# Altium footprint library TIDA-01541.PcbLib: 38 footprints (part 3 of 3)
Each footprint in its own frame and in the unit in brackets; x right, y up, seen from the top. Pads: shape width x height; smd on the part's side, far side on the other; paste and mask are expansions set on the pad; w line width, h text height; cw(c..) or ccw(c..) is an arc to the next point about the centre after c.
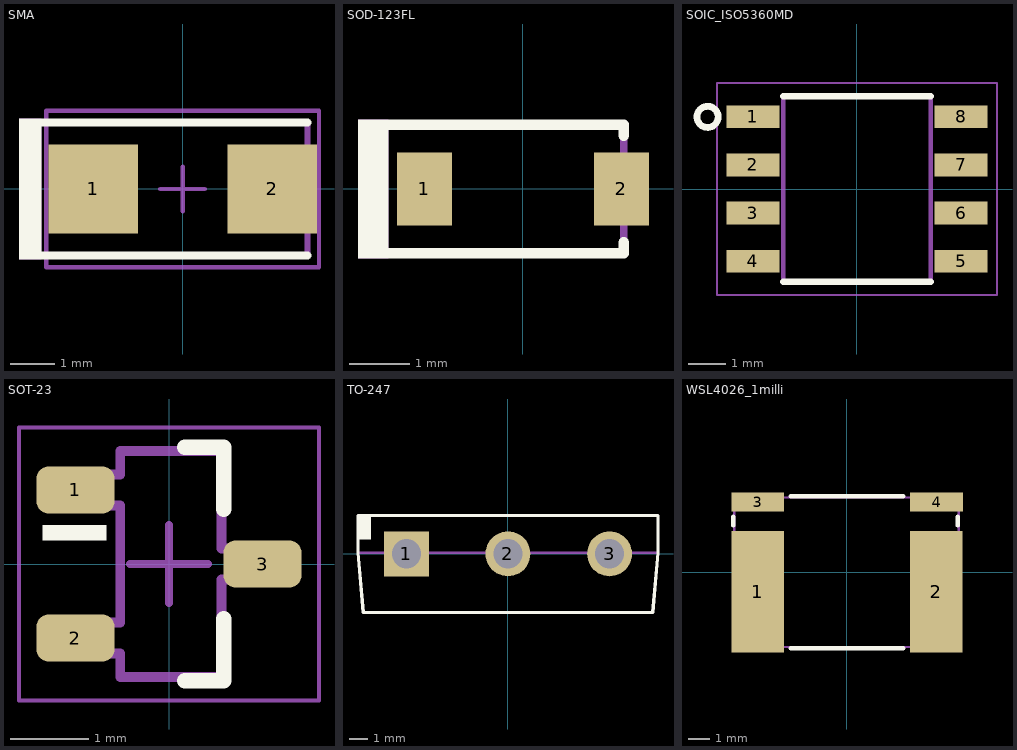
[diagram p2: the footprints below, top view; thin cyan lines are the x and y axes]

## SMA [mm] "Molded Diode, 2-Leads, Body 4.3x2.6mm, IPC Medium Density, based on OnSemi component dimensions and land pattern"
height 2.27
pads (2):
  rect 2x2 smd: 1(-2,0) 2(2,0)
Top Overlay:
  rectangle: -3.658,-1.575 -3.15,1.575
  lines w0.178: -3.327,-1.486 2.794,-1.486 ; -3.327,1.486 2.794,1.486
Mechanical 5:
  rectangle: -3.658,-1.575 -3.15,1.575
  lines w0.127: -3.327,-1.486 2.794,-1.486 2.794,1.486 -3.327,1.486
  text ".Designator" at -0.666,-0.182 h0.76
Mechanical 15:
  lines w0.1: -0.5,0 0.5,0 ; 0,-0.5 0,0.5 ; -3.05,-1.75 3.05,-1.75 3.05,1.75 -3.05,1.75 -3.05,-1.75
3D body "SMA_nominal.stp": height 2.42, standoff 0.02, extent -2.6,-1.3 2.6,1.3

## SOD-123FL [mm] "Copied from SOD-123"
height 0.991
pads (2):
  rect 0.915x1.22 smd: 1(-1.637,0) 2(1.637,0)
Top Overlay:
  rectangle: -2.743,-1.156 -2.235,1.156
  lines w0.178: -2.438,-1.067 1.676,-1.067 1.676,-0.889 ; -2.438,1.067 1.676,1.067 1.676,0.889
Mechanical 5:
  rectangle: -2.743,-1.156 -2.235,1.156
  lines w0.127: -2.438,-1.067 1.676,-1.067 1.676,1.067 -2.438,1.067
  text ".Designator" at 0.406,-0.635 h0.76
3D body "SOD-123FL.stp": height 1, standoff 0, extent -1.9,-0.9 1.9,0.9

## SOIC_ISO5360MD [mm]
height 1.75
pads (8):
  rect 1.4x0.6 smd: 1(-2.75,1.905) 2(-2.75,0.635) 3(-2.75,-0.635) 4(-2.75,-1.905) 5(2.75,-1.905) 6(2.75,-0.635) 7(2.75,0.635) 8(2.75,1.905)
Top Overlay:
  circle w0.178: c-3.945,1.905 r0.279
  lines w0.178: -1.947,-2.452 1.947,-2.452 ; -1.947,2.452 1.947,2.452
Mechanical 5:
  circle w0.127: c-3.945,1.905 r0.279
  lines w0.127: -1.947,-2.452 1.947,-2.452 1.947,2.452 -1.947,2.452 -1.947,-2.452
  text ".Designator" at 0.715,0.449 h0.76
Mechanical 15:
  lines w0.05: -3.7,-2.802 3.7,-2.802 3.7,2.802 -3.7,2.802 -3.7,-2.802
3D body: height 1.75, standoff 0, extent -1.947,-2.452 1.947,2.452

## SOT-23 [mm] "SOT23, 3-Leads, Body 2.9x1.3mm, Pitch 0.95mm, Lead Span 2.5mm, IPC Medium Density"
height 1.1
pads (3):
  rrect50% 1x0.6 smd: 1(-1.2,0.95) 2(-1.2,-0.95) 3(1.2,0)
Top Overlay:
  rectangle: -1.625,0.3 -0.8,0.5
  lines w0.2: 0.2,-1.5 0.7,-1.5 0.7,-0.7 ; 0.2,1.5 0.7,1.5 0.7,0.7
Mechanical 5:
  lines w0.127: -1.16,-1.15 -1.16,-0.75 -0.625,-0.75 -0.625,0.75 -1.16,0.75 -1.16,1.15 -0.625,1.15 -0.625,1.45 0.675,1.45 0.675,0.2 1.21,0.2 1.21,-0.2 0.675,-0.2 0.675,-1.45 -0.625,-1.45 -0.625,-1.15 -1.16,-1.15
  text ".Designator" at -0.356,0.686 h0.76
Mechanical 15:
  lines w0.05: -1.925,-1.75 1.925,-1.75 1.925,1.75 -1.925,1.75 -1.925,-1.75
  lines w0.1: -0.5,0 0.5,0 ; 0,-0.5 0,0.5
3D body "SW3dPS-sot-3p290x130ll237h100.STEP": height 1, standoff 0, extent -1.16,-1.45 1.21,1.45

## TO-247 [mil] "Standard TO-247"
height 1000
pads (3):
  rect 95x95 hole 62: 1(-215,0)
  round 95 / inner round 74.8 / far side round 96 hole 62: 2(0,0) 3(215,0)
Top Overlay:
  rectangle: -317.51,30 -290,81.11
  lines w7: -317.51,2.37 -317.51,81.11 317.53,81.11 317.53,2.37 306.47,-124.01 -306.45,-124.01 -317.51,2.37
Mechanical 5:
  lines w5: -317.51,2.37 317.53,2.37 ; -317.51,2.37 -306.45,-124.01 306.47,-124.01 317.53,2.37 ; -317.51,2.37 -317.51,81.11 317.53,81.11 317.53,2.37
  text ".Designator" at -78.74,-78.74 h30
3D body "TO-274.stp": height 1007.29, standoff -623.42, extent -317.51,-124.01 317.53,81.11

## WSL4026_1milli [mm] "VISHAY"
height 2.88
pads (4):
  rect 2.44x5.6 smd: 1(-4.115,-0.9) 2(4.115,-0.9)
  rect 2.44x0.89 smd: 3(-4.115,3.235) 4(4.135,3.235)
Top Overlay:
  lines w0.2: -5.25,2.15 -5.25,2.55 ; -2.6,-3.5 2.6,-3.5 ; -2.6,3.5 2.6,3.5 ; 5.1,2.15 5.1,2.55
Mechanical 5:
  lines w0.1: -5.2,-3.45 -5.2,3.45 5.15,3.45 5.15,-3.45 -5.2,-3.45
  text ".Designator" at 0.457,-1.372 h0.76
3D body "Vishay_WSL4026_1milli.stp": height 2.88, standoff 0, extent -5.15,-3.25 5.15,3.65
